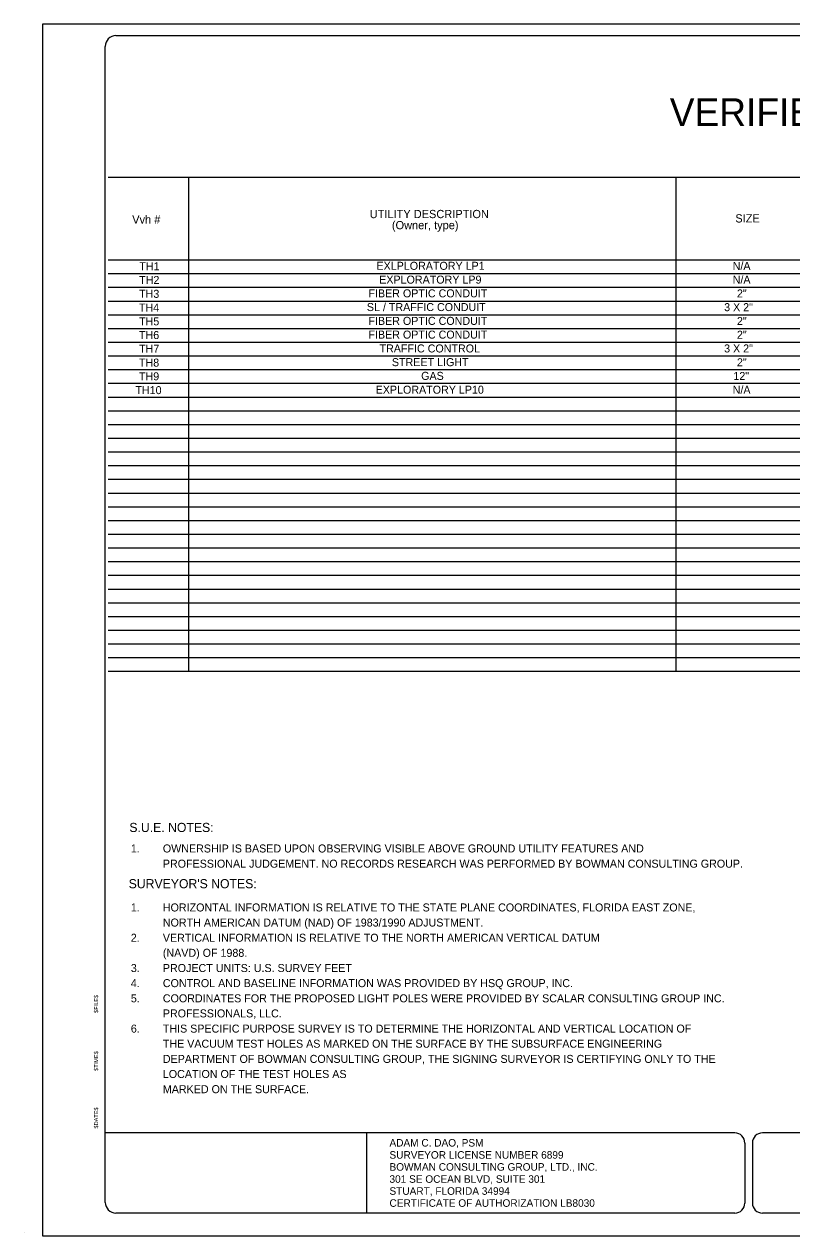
# Model space of a CAD drawing. Extents: x -769.4 to -731.2, y -2181.6 to -2171.
# Drawn here: x -769.36 to -762.64, y -2181.58 to -2170.98 of the extents above; entities that cross this region are included whole.
import ezdxf

# ---------------------------------------------------------------- set-up
doc = ezdxf.new("R2010")
doc.units = 0
for name, color, linetype in [('AdhocPoint_dp', 7, 'Continuous'), ('Default', 7, 'Continuous'), ('PlotBorder_dp', 7, 'Continuous'), ('TextNotes', 7, 'Continuous'), ('TextSurveyLabel', 7, 'Continuous')]:
    doc.layers.add(name, color=color, linetype=linetype)

msp = doc.modelspace()

# ---------------------------------------------------------------- linework, layer by layer
at = {"layer": 'AdhocPoint_dp'}
msp.add_line((-769.359, -2181.552), (-769.359, -2181.552), dxfattribs=at)
at = {"layer": 'Default'}
for p, q in [((-753.325, -2171.082), (-768.557, -2171.082)), ((-768.65, -2181.289), (-768.65, -2171.175)), ((-763.142, -2180.681), (-768.65, -2180.681)), ((-766.362, -2181.383), (-766.362, -2180.681)), ((-762.415, -2180.681), (-762.9, -2180.681)), ((-763.054, -2180.77), (-763.054, -2181.295)), ((-762.988, -2180.77), (-762.988, -2181.295)), ((-763.142, -2181.383), (-768.557, -2181.383)), ((-762.415, -2181.383), (-762.9, -2181.383))]:
    msp.add_line(p, q, dxfattribs=at)
for centre, major_axis, start_param, end_param in [((-768.557, -2171.175), (0, -0.0935), 3.141593, 4.712389), ((-763.142, -2180.77), (0, 0.0882), 4.712389, 6.283185), ((-762.9, -2180.77), (0, 0.0882), 0, 1.570796), ((-768.557, -2181.289), (0, -0.0935), 4.712389, 6.283185), ((-763.142, -2181.295), (0, 0.0882), 3.141593, 4.712389), ((-762.9, -2181.295), (0, -0.0882), 4.712389, 6.283185)]:
    msp.add_ellipse(centre, major_axis=major_axis, ratio=0.999927, start_param=start_param, end_param=end_param, dxfattribs=at)
at = {"layer": 'PlotBorder_dp'}
msp.add_lwpolyline([(-769.2, -2181.581), (-752.7, -2181.581), (-752.7, -2170.981), (-769.2, -2170.981)], close=True, dxfattribs=at)
at = {"layer": 'TextSurveyLabel'}
for p, q in [((-768.623, -2172.32), (-753.223, -2172.32)), ((-768.583, -2172.32), (-753.223, -2172.32)), ((-767.922, -2172.32), (-767.922, -2176.643)), ((-763.658, -2172.32), (-763.658, -2176.643)), ((-768.623, -2173.043), (-753.223, -2173.043)), ((-768.623, -2173.163), (-753.223, -2173.163)), ((-768.623, -2173.283), (-753.223, -2173.283)), ((-768.623, -2173.403), (-753.223, -2173.403)), ((-768.623, -2173.523), (-753.223, -2173.523)), ((-768.623, -2173.643), (-753.223, -2173.643)), ((-768.623, -2173.763), (-753.223, -2173.763)), ((-768.623, -2173.883), (-753.223, -2173.883)), ((-768.623, -2174.003), (-753.223, -2174.003)), ((-768.623, -2174.123), (-753.223, -2174.123)), ((-768.623, -2174.243), (-753.223, -2174.243)), ((-768.623, -2174.363), (-753.223, -2174.363)), ((-768.623, -2174.483), (-753.223, -2174.483)), ((-768.623, -2174.603), (-753.223, -2174.603)), ((-768.623, -2174.723), (-753.223, -2174.723)), ((-768.623, -2174.843), (-753.223, -2174.843)), ((-768.623, -2174.963), (-753.223, -2174.963)), ((-768.623, -2175.083), (-753.223, -2175.083)), ((-768.623, -2175.203), (-753.223, -2175.203)), ((-768.623, -2175.323), (-753.223, -2175.323)), ((-768.623, -2175.443), (-753.223, -2175.443)), ((-768.623, -2175.563), (-753.223, -2175.563)), ((-768.623, -2175.683), (-753.223, -2175.683)), ((-768.623, -2175.803), (-753.223, -2175.803)), ((-768.623, -2175.923), (-753.223, -2175.923)), ((-768.623, -2176.043), (-753.223, -2176.043)), ((-768.623, -2176.163), (-753.223, -2176.163)), ((-768.623, -2176.283), (-753.223, -2176.283)), ((-768.623, -2176.403), (-753.223, -2176.403)), ((-768.623, -2176.523), (-753.223, -2176.523)), ((-768.623, -2176.643), (-753.223, -2176.643))]:
    msp.add_line(p, q, dxfattribs=at)

# ---------------------------------------------------------------- texts
at = {"layer": 'Default'}
for s, p in [('$FILE$', (-768.712, -2179.631)), ('$TIME$', (-768.712, -2180.138)), ('$DATE$', (-768.712, -2180.643))]:
    msp.add_text(s, height=0.0354, rotation=90, dxfattribs=at).set_placement(p)
at = {"layer": 'TextNotes'}
for s, p in [('ADAM C. DAO, PSM', (-766.163, -2180.801)), ('SURVEYOR LICENSE NUMBER 6899', (-766.163, -2180.907)), ('BOWMAN CONSULTING GROUP, LTD., INC.', (-766.163, -2181.012)), ('301 SE OCEAN BLVD, SUITE 301          ', (-766.163, -2181.118)), ('STUART, FLORIDA 34994                 ', (-766.163, -2181.223)), ('CERTIFICATE OF AUTHORIZATION LB8030', (-766.163, -2181.328))]:
    msp.add_text(s, height=0.0659, rotation=360, dxfattribs=at).set_placement(p)
at = {"layer": 'TextSurveyLabel'}
for s, height, p in [('   VERIFIED UTILITY LOCATE   ', 0.24265, (-763.981, -2171.872)), ('Vvh #', 0.072, (-768.414, -2172.726)), ('UTILITY DESCRIPTION', 0.072, (-766.336, -2172.678)), ('SIZE', 0.072, (-763.137, -2172.716)), ('(Owner, type)', 0.072, (-766.142, -2172.775)), ('TH1', 0.07, (-768.352, -2173.134)), ('EXLPLORATORY LP1 ', 0.07, (-766.277, -2173.13)), ('N/A', 0.07, (-763.16, -2173.131)), ('TH2', 0.07, (-768.353, -2173.254)), ('EXPLORATORY LP9', 0.07, (-766.253, -2173.251)), ('N/A', 0.07, (-763.16, -2173.251)), ('TH3', 0.07, (-768.354, -2173.375)), ('FIBER OPTIC CONDUIT', 0.07, (-766.347, -2173.371)), ('2"', 0.07, (-763.123, -2173.372)), ('SL / TRAFFIC CONDUIT', 0.07, (-766.361, -2173.491)), ('3 X 2"', 0.07, (-763.235, -2173.492)), ('TH4', 0.07, (-768.355, -2173.495)), ('TH5', 0.07, (-768.354, -2173.616)), ('FIBER OPTIC CONDUIT', 0.07, (-766.347, -2173.612)), ('2"', 0.07, (-763.123, -2173.613)), ('TH6', 0.07, (-768.355, -2173.736)), ('FIBER OPTIC CONDUIT', 0.07, (-766.347, -2173.732)), ('2"', 0.07, (-763.123, -2173.733)), ('TH7', 0.07, (-768.354, -2173.856)), ('TRAFFIC CONTROL', 0.07, (-766.25, -2173.853)), ('3 X 2"', 0.07, (-763.235, -2173.853)), ('TH8', 0.07, (-768.355, -2173.977)), ('STREET LIGHT', 0.07, (-766.142, -2173.973)), ('2"', 0.07, (-763.123, -2173.974)), ('TH9', 0.07, (-768.355, -2174.097)), ('GAS', 0.07, (-765.886, -2174.093)), ('12"', 0.07, (-763.154, -2174.094)), ('TH10', 0.07, (-768.386, -2174.218)), ('EXPLORATORY LP10', 0.07, (-766.284, -2174.214)), ('N/A', 0.07, (-763.16, -2174.215)), ('1.', 0.07, (-768.426, -2178.744)), ('HORIZONTAL INFORMATION IS RELATIVE TO THE STATE PLANE COORDINATES, FLORIDA EAST ZONE, ', 0.07, (-768.146, -2178.744)), ('NORTH AMERICAN DATUM (NAD) OF 1983/1990 ADJUSTMENT.', 0.07, (-768.146, -2178.876)), ('2.', 0.07, (-768.426, -2179.009)), ('VERTICAL INFORMATION IS RELATIVE TO THE NORTH AMERICAN VERTICAL DATUM', 0.07, (-768.146, -2179.009)), ('(NAVD) OF 1988.', 0.07, (-768.146, -2179.141)), ('3.', 0.07, (-768.426, -2179.274)), ('PROJECT UNITS: U.S. SURVEY FEET', 0.07, (-768.146, -2179.274)), ('4.', 0.07, (-768.426, -2179.406)), ('CONTROL AND BASELINE INFORMATION WAS PROVIDED BY HSQ GROUP, INC.', 0.07, (-768.146, -2179.406)), ('5.', 0.07, (-768.426, -2179.539)), ('COORDINATES FOR THE PROPOSED LIGHT POLES WERE PROVIDED BY SCALAR CONSULTING GROUP INC. ', 0.07, (-768.146, -2179.539)), ('PROFESSIONALS, LLC.', 0.07, (-768.146, -2179.671)), ('6.', 0.07, (-768.426, -2179.804)), ('THIS SPECIFIC PURPOSE SURVEY IS TO DETERMINE THE HORIZONTAL AND VERTICAL LOCATION OF ', 0.07, (-768.146, -2179.804)), ('THE VACUUM TEST HOLES AS MARKED ON THE SURFACE BY THE SUBSURFACE ENGINEERING ', 0.07, (-768.146, -2179.936)), ('DEPARTMENT OF BOWMAN CONSULTING GROUP, THE SIGNING SURVEYOR IS CERTIFYING ONLY TO THE ', 0.07, (-768.146, -2180.069)), ('LOCATION OF THE TEST HOLES AS ', 0.07, (-768.146, -2180.201)), ('MARKED ON THE SURFACE.  ', 0.07, (-768.146, -2180.334))]:
    msp.add_text(s, height=height, dxfattribs=at).set_placement(p)
for s, height, p in [('S.U.E. NOTES:', 0.08, (-768.439, -2178.049)), ('1.', 0.07, (-768.426, -2178.228)), ('OWNERSHIP IS BASED UPON OBSERVING VISIBLE ABOVE GROUND UTILITY FEATURES AND ', 0.07, (-768.146, -2178.228)), ('PROFESSIONAL JUDGEMENT. NO RECORDS RESEARCH WAS PERFORMED BY BOWMAN CONSULTING GROUP.', 0.07, (-768.146, -2178.361)), ("SURVEYOR'S NOTES:", 0.08, (-768.445, -2178.541))]:
    msp.add_text(s, height=height, rotation=360, dxfattribs=at).set_placement(p)

doc.saveas('drawing.dxf')
